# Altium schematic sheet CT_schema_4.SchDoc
size 469 x 363 mm
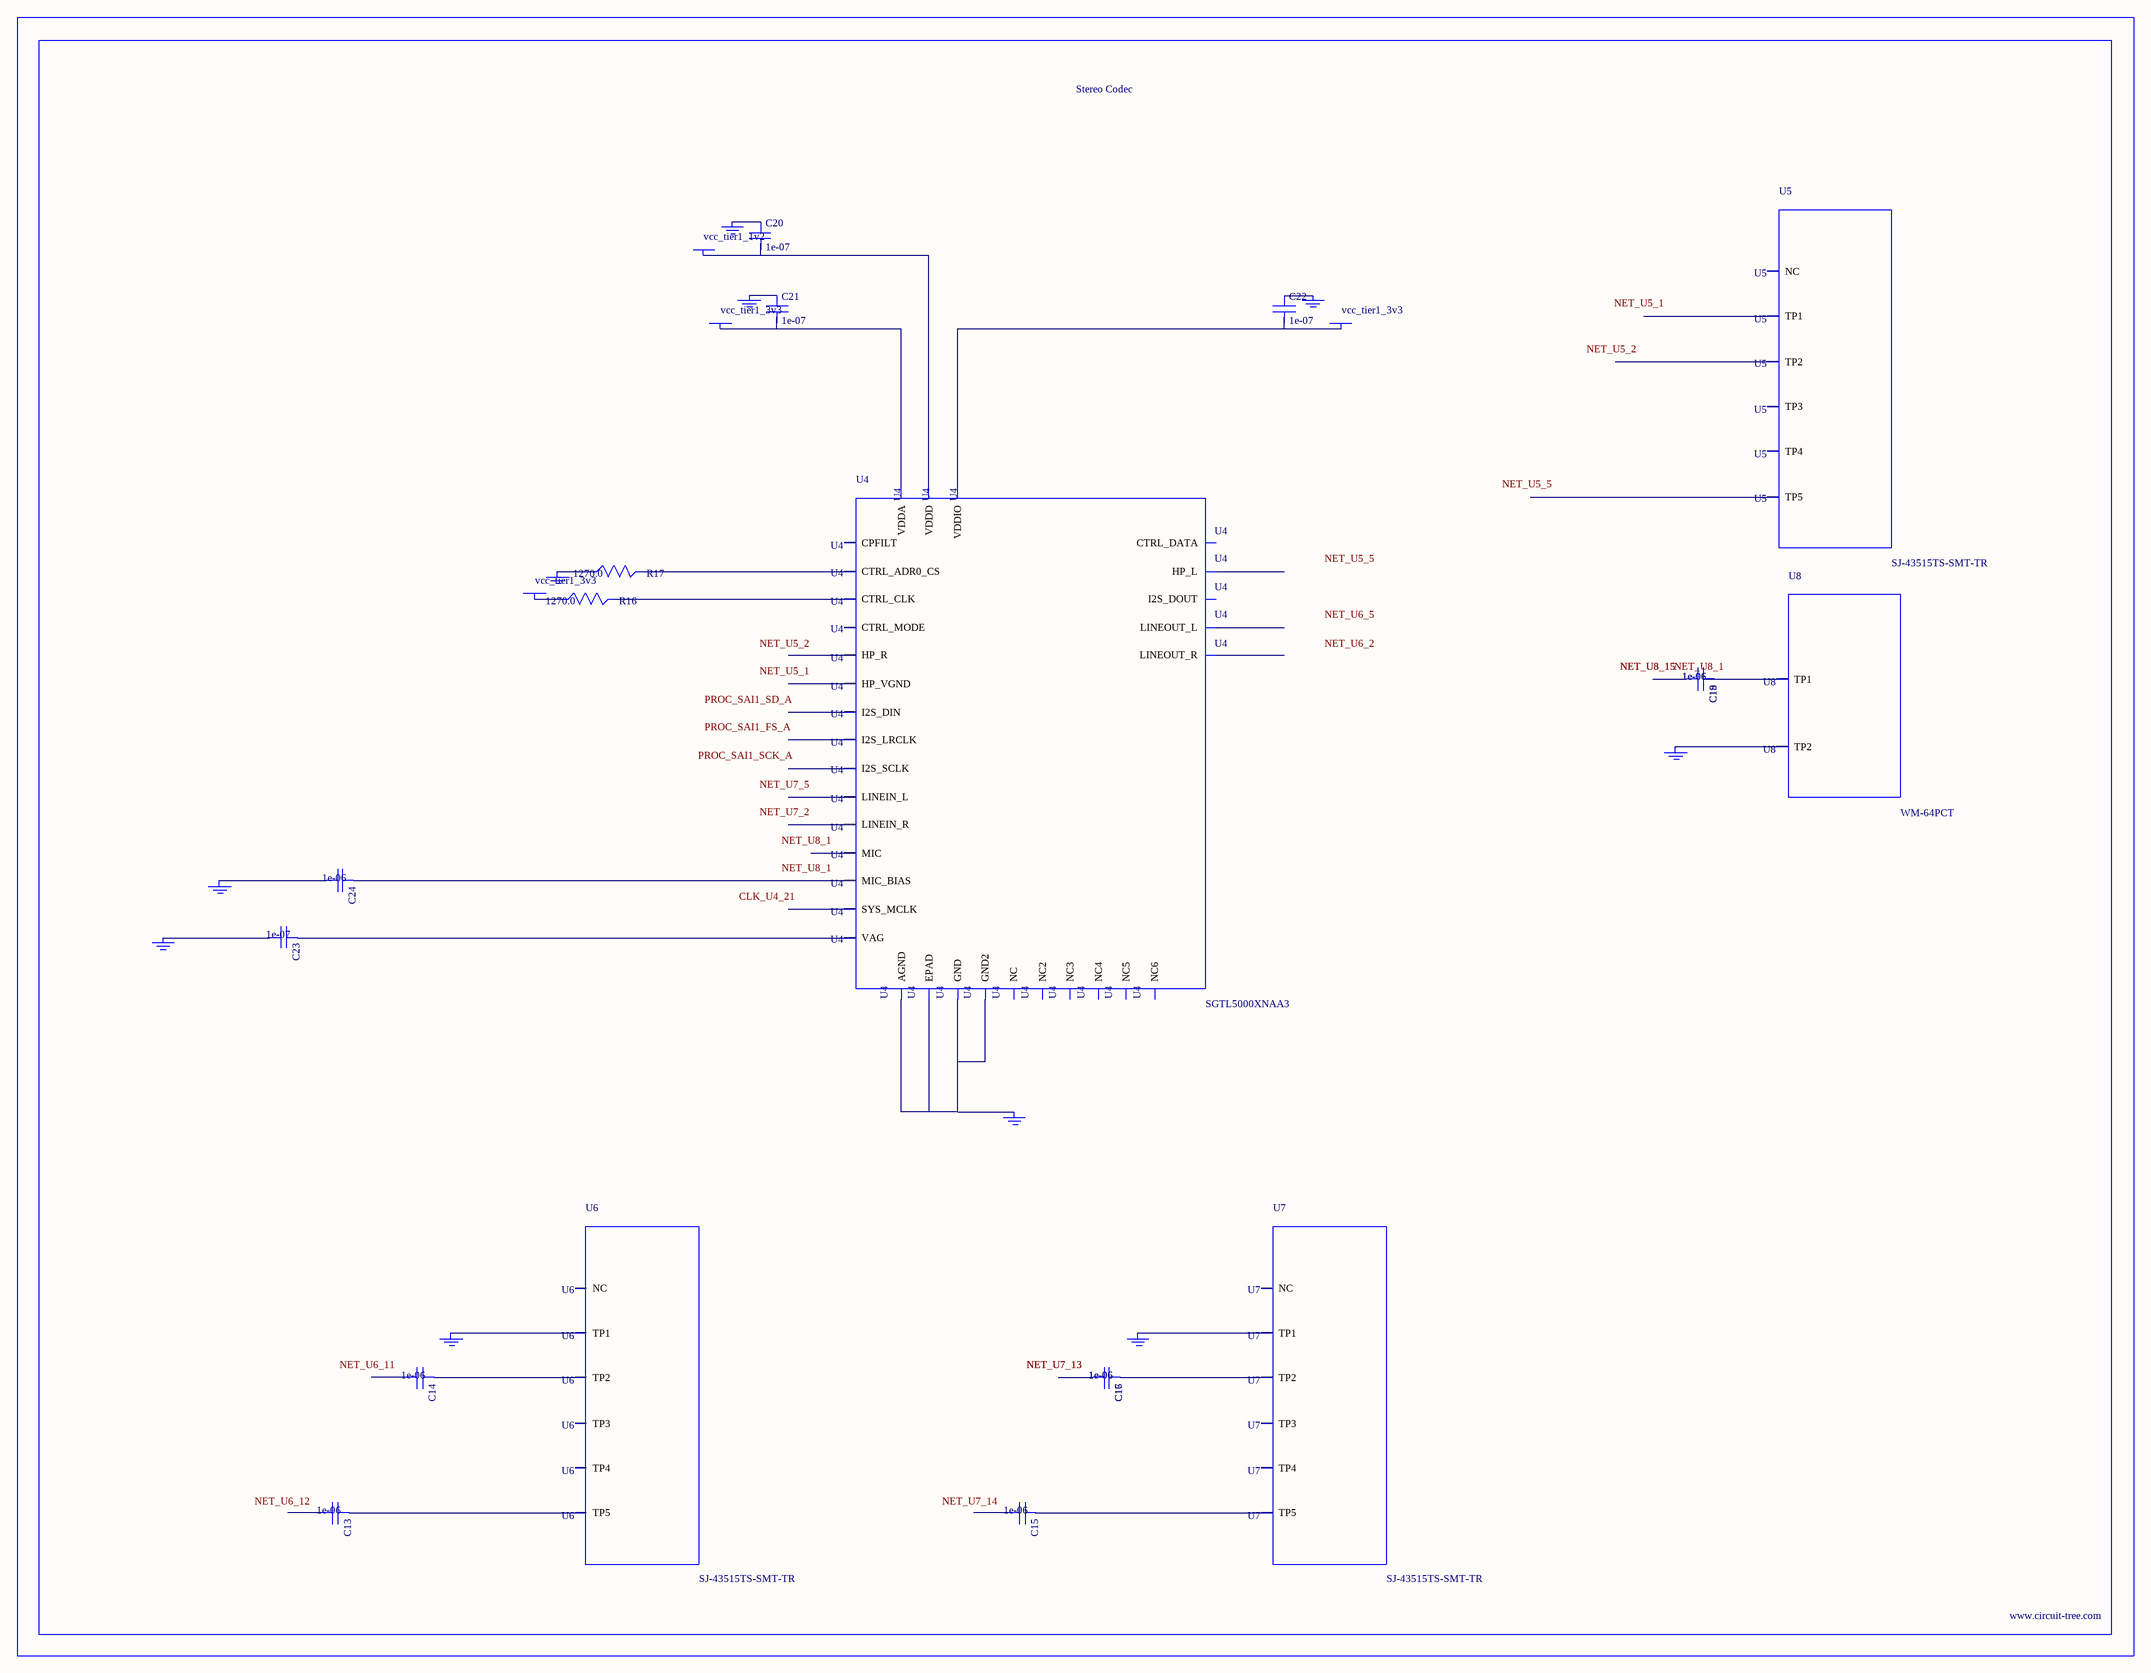
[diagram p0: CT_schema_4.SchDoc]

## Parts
BORDER3  (no value)
C13  1e-06  [C0603]
C14  1e-06  [C0603]
C15  1e-06  [C0603]
C16  1e-06  [C0603]
C17  1e-06  [C0603]
C18  1e-06  [C0603]
C19  1e-06  [C0603]
C20  1e-07  [C0402]
C21  1e-07  [C0402]
C22  1e-07  [C0402]
C23  1e-07  [C0402]
C24  1e-06  [C0603]
GND_INSTANCE_3_0  (no value)
GND_INSTANCE_3_1  (no value)
GND_INSTANCE_3_2  (no value)
GND_INSTANCE_3_3  (no value)
GND_INSTANCE_3_4  (no value)
GND_INSTANCE_3_5  (no value)
GND_INSTANCE_3_6  (no value)
GND_INSTANCE_3_7  (no value)
GND_INSTANCE_3_8  (no value)
GND_INSTANCE_3_9  (no value)
GND_INSTANCE_3_10  (no value)
POWER_INSTANCE_3_0  vcc_tier1_3v3
POWER_INSTANCE_3_1  vcc_tier1_3v3
POWER_INSTANCE_3_2  vcc_tier1_3v3
POWER_INSTANCE_3_3  vcc_tier1_1v2
R16  1270.0  [R0603]
R17  1270.0  [R0603]
U4  SGTL5000XNAA3  [QFN-32]
U5  SJ-43515TS-SMT-TR  [SJ-43515TS-SMT-TR]
U6  SJ-43515TS-SMT-TR  [SJ-43515TS-SMT-TR]
U7  SJ-43515TS-SMT-TR  [SJ-43515TS-SMT-TR]
U8  WM-64PCT  [WM-64PC]

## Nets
NetC13_1: C13.1 U6.5(TP5)
NetC14_1: C14.1 U6.2(TP2)
NetC15_1: C15.1 U7.5(TP5)
NetC16_1: C16.1 C17.1 U7.2(TP2)
NetC16_2: C16.2 C17.2
NetC18_1: C18.1 C19.1 U8.1(TP1)
NetC18_2: C18.2 C19.2
NetC20_1: C20.1 GND_INSTANCE_3_5.0(GND)
NetC20_2: C20.2 POWER_INSTANCE_3_3.0(PWR) U4.30(VDDD)
NetC21_1: C21.1 GND_INSTANCE_3_1.0(GND)
NetC21_2: C21.2 POWER_INSTANCE_3_0.0(PWR) U4.5(VDDA)
NetC22_1: C22.1 GND_INSTANCE_3_4.0(GND)
NetC22_2: C22.2 POWER_INSTANCE_3_1.0(PWR) U4.20(VDDIO)
NetC23_1: C23.1 U4.10(VAG)
NetC23_2: C23.2 GND_INSTANCE_3_2.0(GND)
NetC24_1: C24.1 U4.16(MIC_BIAS)
NetC24_2: C24.2 GND_INSTANCE_3_3.0(GND)
NetGND_INSTANCE_3_0_0: GND_INSTANCE_3_0.0(GND) U4.1(GND) U4.3(GND2) U4.7(AGND) U4.EXP(EPAD)
NetGND_INSTANCE_3_6_0: GND_INSTANCE_3_6.0(GND) R17.1
NetGND_INSTANCE_3_7_0: GND_INSTANCE_3_7.0(GND) U6.1(TP1)
NetGND_INSTANCE_3_8_0: GND_INSTANCE_3_8.0(GND) GND_INSTANCE_3_9.0(GND) U7.1(TP1)
NetGND_INSTANCE_3_10_0: GND_INSTANCE_3_10.0(GND) U8.2(TP2)
NetPOWER_INSTANCE_3_2_0: POWER_INSTANCE_3_2.0(PWR) R16.1
NetR16_2: R16.2 U4.29(CTRL_CLK)
NetR17_2: R17.2 U4.31(CTRL_ADR0_CS)

Not connected (* = marked no-connect by the designer): C13 2; C14 2; C15 2; U4 2(HP_R) 4(HP_VGND) 6(HP_L) 8(NC) 9(NC2) 11(LINEOUT_R) 12(LINEOUT_L) 13(LINEIN_R) 14(LINEIN_L) 15(MIC) 17(NC3) 18(CPFILT) 19(NC4) 21(SYS_MCLK) 22(NC5) 23(I2S_LRCLK) 24(I2S_SCLK) 25(I2S_DOUT) 26(I2S_DIN) 27(CTRL_DATA) 28(NC6) 32(CTRL_MODE); U5 1(TP1) 2(TP2) 3(TP3) 4(TP4) 5(TP5) 6(NC); U6 3(TP3) 4(TP4) 6(NC); U7 3(TP3) 4(TP4) 6(NC)

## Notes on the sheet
- Labels drawn without touching a wire or pin: CLK_U4_21, NET_U5_1, NET_U5_2, NET_U5_5, NET_U6_2, NET_U6_5, NET_U6_11, NET_U6_12, NET_U7_2, NET_U7_5, NET_U7_14, NET_U8_1, PROC_SAI1_FS_A, PROC_SAI1_SCK_A, PROC_SAI1_SD_A

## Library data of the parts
BORDER3 = BORDER_PAGE3
C13-C19 C24 = C0603C105K3RACTU
C20-C23 = C0402C104K3RACTU
GND_INSTANCE_3_0-GND_INSTANCE_3_10 = GND
POWER_INSTANCE_3_0-POWER_INSTANCE_3_3 = PWR
R16 R17 = RC0603FR-071K27L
